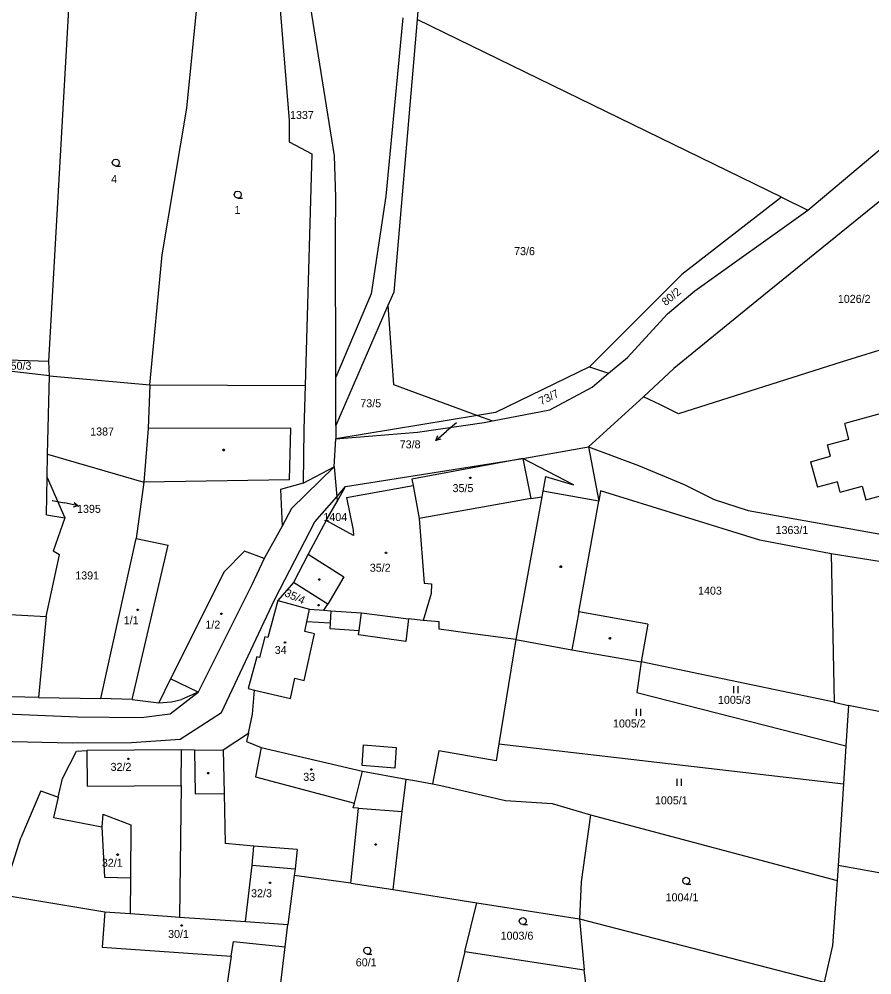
# Model space of a CAD drawing. Extents: x -852001 to -842497, y -1063614 to -1052182.
# Drawn here: x -844444 to -844262.9, y -1061526.1 to -1061323.1 of the extents above; entities that cross this region are included whole.
import ezdxf

# ---------------------------------------------------------------- set-up
doc = ezdxf.new("R2010")
doc.units = 0
for name, color, linetype in [('Default', 7, 'Continuous'), ('KN_HRANICE', 7, 'Continuous'), ('KN_KULTURY', 7, 'Continuous'), ('KN_PARCELY', 7, 'Continuous'), ('KN_SLUCKY', 7, 'Continuous')]:
    doc.layers.add(name, color=color, linetype=linetype)

# ---------------------------------------------------------------- blocks, each defined once
blk = doc.blocks.new('304')
at = {"layer": 'Default'}
blk.add_lwpolyline([(0, 0), (-0.38, 0.1), (-0.65, 0.37), (-0.75, 0.74), (-0.65, 1.11), (-0.38, 1.38), (-0.01, 1.48), (0.36, 1.38), (0.63, 1.11), (0.73, 0.73), (0.63, 0.35), (0.36, 0.08), (-0.02, -0.02), (0.98, -0.02)], dxfattribs=at)
blk = doc.blocks.new('306')
at = {"layer": 'Default'}
for p, q in [((-0.5, 1.5), (-0.5, 0)), ((0.5, 0), (0.5, 1.5))]:
    blk.add_line(p, q, dxfattribs=at)
blk = doc.blocks.new('NAHRADNI_SYMBOL')
at = {"layer": 'Default'}
blk.add_lwpolyline([(0.09, 0.15), (0.18, 0), (0.09, -0.15), (-0.09, -0.15), (-0.18, 0), (-0.09, 0.15), (0.09, 0.15)], dxfattribs=at)
blk = doc.blocks.new('10292')
at = {"layer": 'Default'}
blk.add_line((0, 3), (0, 0), dxfattribs=at)
blk.add_lwpolyline([(-0.5, 2), (0, 3), (0.5, 2)], dxfattribs=at)
blk = doc.blocks.new('402')
at = {"layer": 'Default'}
blk.add_lwpolyline([(0.09, 0.15), (0.18, 0), (0.09, -0.15), (-0.09, -0.15), (-0.18, 0), (-0.09, 0.15), (0.09, 0.15)], dxfattribs=at)

msp = doc.modelspace()

# ---------------------------------------------------------------- linework, layer by layer
at = {"layer": 'KN_HRANICE'}
for p, q in [((-844355.8, -1061278.6), (-844359.49, -1061323.11)), ((-844437.76, -1061395.7), (-844432.89, -1061310.51)), ((-844408.43, -1061341.94), (-844405.53, -1061312.84)), ((-844389.08, -1061315.26), (-844386.69, -1061344.57)), ((-844377.08, -1061352.12), (-844382.88, -1061315.51)), ((-844362.55, -1061322.76), (-844366.12, -1061360.65)), ((-844359.49, -1061323.11), (-844364.48, -1061381.09)), ((-844282.06, -1061360.88), (-844359.49, -1061323.11)), ((-844276.49, -1061363.63), (-844241.6, -1061334.29)), ((-844413.69, -1061373.1), (-844408.43, -1061341.94)), ((-844386.69, -1061344.57), (-844386.69, -1061349.14)), ((-844386.69, -1061349.14), (-844381.84, -1061351.65)), ((-844381.84, -1061351.65), (-844383.28, -1061400.88)), ((-844376.79, -1061360.87), (-844377.08, -1061352.12)), ((-844255.48, -1061357.05), (-844287.3, -1061382.9)), ((-844376.86, -1061369.32), (-844376.79, -1061360.87)), ((-844366.12, -1061360.65), (-844369.26, -1061381.41)), ((-844282.06, -1061360.88), (-844303.29, -1061377.34)), ((-844282.06, -1061360.88), (-844276.49, -1061363.63)), ((-844300.54, -1061380.81), (-844276.49, -1061363.63)), ((-844376.78, -1061399.14), (-844376.86, -1061369.32)), ((-844416.28, -1061400.77), (-844413.69, -1061373.1)), ((-844303.29, -1061377.34), (-844322.91, -1061396.91)), ((-844369.26, -1061381.41), (-844376.78, -1061399.14)), ((-844364.48, -1061381.09), (-844365.7, -1061383.91)), ((-844306.31, -1061385.64), (-844300.54, -1061380.81)), ((-844365.7, -1061383.91), (-844376.75, -1061409.41)), ((-844365.7, -1061383.91), (-844364.51, -1061400.66)), ((-844287.3, -1061382.9), (-844304.99, -1061397.3)), ((-844314.83, -1061394.93), (-844306.31, -1061385.64)), ((-844234.19, -1061384.88), (-844269.23, -1061395.89)), ((-844475.97, -1061394.54), (-844437.76, -1061395.7)), ((-844437.56, -1061398.83), (-844475.97, -1061394.54)), ((-844437.56, -1061398.83), (-844437.76, -1061395.7)), ((-844318.83, -1061398.3), (-844314.83, -1061394.93)), ((-844269.23, -1061395.89), (-844303.98, -1061406.9)), ((-844322.91, -1061396.91), (-844342.88, -1061406.62)), ((-844322.91, -1061396.91), (-844318.83, -1061398.3)), ((-844322.33, -1061401.24), (-844318.83, -1061398.3)), ((-844304.99, -1061397.3), (-844311.38, -1061403.28)), ((-844438.01, -1061415.47), (-844437.56, -1061398.83)), ((-844437.56, -1061398.83), (-844416.28, -1061400.77)), ((-844376.75, -1061409.41), (-844376.78, -1061399.14)), ((-844364.51, -1061400.66), (-844346.64, -1061407.24)), ((-844416.28, -1061400.77), (-844416.62, -1061410.01)), ((-844416.28, -1061400.77), (-844383.28, -1061400.88)), ((-844383.28, -1061400.88), (-844383.55, -1061410.22)), ((-844331.28, -1061406.1), (-844322.33, -1061401.24)), ((-844311.38, -1061403.28), (-844323.12, -1061413.92)), ((-844307.8, -1061405.03), (-844311.38, -1061403.28)), ((-844342.88, -1061406.62), (-844346.64, -1061407.24)), ((-844343.46, -1061408.4), (-844331.28, -1061406.1)), ((-844303.98, -1061406.9), (-844307.8, -1061405.03)), ((-844259.62, -1061406.48), (-844268.64, -1061408.96)), ((-844346.64, -1061407.24), (-844376.75, -1061412.24)), ((-844359.4, -1061410.79), (-844345.26, -1061408.74)), ((-844346.64, -1061407.24), (-844343.46, -1061408.4)), ((-844345.26, -1061408.74), (-844343.46, -1061408.4)), ((-844416.62, -1061410.01), (-844417.56, -1061421.43)), ((-844383.55, -1061410.22), (-844383.68, -1061421.62)), ((-844376.75, -1061409.41), (-844376.75, -1061412.24)), ((-844376.75, -1061412.24), (-844359.4, -1061410.79)), ((-844267.77, -1061412.3), (-844268.64, -1061408.96)), ((-844377.11, -1061418.19), (-844376.75, -1061412.24)), ((-844272.32, -1061413.52), (-844267.77, -1061412.3)), ((-844337.01, -1061416.42), (-844323.12, -1061413.92)), ((-844323.12, -1061413.92), (-844320.91, -1061425.5)), ((-844323.12, -1061413.92), (-844312.48, -1061417.88)), ((-844271.7, -1061415.94), (-844272.32, -1061413.52)), ((-844438.09, -1061420.42), (-844438.01, -1061415.47)), ((-844438.01, -1061415.47), (-844417.56, -1061421.43)), ((-844374.69, -1061422.36), (-844337.01, -1061416.42)), ((-844337.01, -1061416.42), (-844360.59, -1061420.77)), ((-844275.92, -1061417.08), (-844271.7, -1061415.94)), ((-844383.68, -1061421.62), (-844377.11, -1061418.19)), ((-844377.11, -1061418.19), (-844376.59, -1061424.54)), ((-844312.48, -1061417.88), (-844302.78, -1061421.94)), ((-844275.92, -1061417.08), (-844274.43, -1061422.48)), ((-844438.22, -1061428.35), (-844438.09, -1061420.42)), ((-844438.09, -1061420.42), (-844434.36, -1061428.99)), ((-844360.59, -1061420.77), (-844360.31, -1061422.11)), ((-844417.56, -1061421.43), (-844419.19, -1061433.37)), ((-844383.68, -1061421.62), (-844388.49, -1061423.02)), ((-844388.49, -1061423.02), (-844388.18, -1061430.75)), ((-844376.51, -1061425.55), (-844374.69, -1061422.36)), ((-844374.53, -1061424.7), (-844360.31, -1061422.11)), ((-844360.31, -1061422.11), (-844359.06, -1061429.16)), ((-844302.78, -1061421.94), (-844296.41, -1061425.13)), ((-844270.17, -1061421.34), (-844274.43, -1061422.48)), ((-844269.61, -1061423.58), (-844270.17, -1061421.34)), ((-844269.61, -1061423.58), (-844264.95, -1061422.29)), ((-844264.95, -1061422.29), (-844264.16, -1061425.17)), ((-844264.16, -1061425.17), (-844255.09, -1061422.7)), ((-844376.59, -1061424.54), (-844376.51, -1061425.55)), ((-844374.53, -1061424.7), (-844373.11, -1061431.65)), ((-844320.54, -1061423.3), (-844320.91, -1061425.5)), ((-844286.69, -1061433.79), (-844320.54, -1061423.3)), ((-844378.81, -1061429.57), (-844376.51, -1061425.55)), ((-844325.16, -1061448.99), (-844320.91, -1061425.5)), ((-844296.41, -1061425.13), (-844289.17, -1061427.44)), ((-844438.22, -1061428.35), (-844434.36, -1061428.99)), ((-844434.36, -1061428.99), (-844436.82, -1061436.08)), ((-844289.17, -1061427.44), (-844237.33, -1061436.72)), ((-844388.18, -1061430.75), (-844391.97, -1061437.66)), ((-844378.81, -1061429.57), (-844382.68, -1061436.7)), ((-844372.98, -1061432.73), (-844378.81, -1061429.57)), ((-844359.06, -1061429.16), (-844357.98, -1061442.87)), ((-844373.11, -1061431.65), (-844372.98, -1061432.73)), ((-844426.7, -1061467.38), (-844419.19, -1061433.37)), ((-844271.55, -1061436.64), (-844286.69, -1061433.79)), ((-844438.29, -1061449.97), (-844435.49, -1061436.86)), ((-844435.49, -1061436.86), (-844436.82, -1061436.08)), ((-844396.14, -1061436.12), (-844400.48, -1061440.48)), ((-844391.97, -1061437.66), (-844396.14, -1061436.12)), ((-844382.68, -1061436.7), (-844385.79, -1061442.75)), ((-844213.45, -1061446), (-844271.55, -1061436.64)), ((-844271.55, -1061436.64), (-844270.91, -1061468.18)), ((-844391.97, -1061437.66), (-844394.6, -1061443.25)), ((-844400.48, -1061440.48), (-844411.86, -1061463.19)), ((-844394.6, -1061443.25), (-844405.99, -1061466.08)), ((-844385.79, -1061442.75), (-844389.07, -1061446.6)), ((-844378.49, -1061447.34), (-844385.79, -1061442.75)), ((-844357.98, -1061442.87), (-844356.44, -1061443.03)), ((-844356.44, -1061443.03), (-844356.52, -1061445.06)), ((-844356.52, -1061445.06), (-844358.19, -1061450.8)), ((-844389.07, -1061446.6), (-844391.21, -1061454.46)), ((-844389.07, -1061446.6), (-844382.35, -1061448.45)), ((-844379.31, -1061448.65), (-844378.49, -1061447.34)), ((-844454.2, -1061449.07), (-844438.29, -1061449.97)), ((-844382.35, -1061448.45), (-844379.31, -1061448.65)), ((-844379.31, -1061448.65), (-844377.86, -1061448.74)), ((-844377.86, -1061448.74), (-844371.34, -1061449.16)), ((-844371.34, -1061449.16), (-844361.33, -1061450.48)), ((-844310.49, -1061451.61), (-844325.16, -1061448.99)), ((-844438.29, -1061449.97), (-844439.9, -1061467.16)), ((-844358.19, -1061450.8), (-844361.33, -1061450.48)), ((-844354.84, -1061451.14), (-844358.19, -1061450.8)), ((-844354.84, -1061452.65), (-844354.84, -1061451.14)), ((-844348.7, -1061453.49), (-844354.84, -1061452.65)), ((-844338.51, -1061454.86), (-844348.7, -1061453.49)), ((-844310.49, -1061451.61), (-844311.93, -1061459.63)), ((-844391.82, -1061454.3), (-844393.01, -1061458.7)), ((-844391.21, -1061454.46), (-844391.82, -1061454.3)), ((-844338.51, -1061454.86), (-844342.11, -1061477.05)), ((-844338.51, -1061454.86), (-844326.62, -1061457.05)), ((-844326.62, -1061457.05), (-844311.93, -1061459.63)), ((-844393.54, -1061458.56), (-844395.36, -1061465.26)), ((-844393.01, -1061458.7), (-844393.54, -1061458.56)), ((-844311.93, -1061459.63), (-844312.83, -1061466.13)), ((-844270.91, -1061468.18), (-844311.93, -1061459.63)), ((-844411.86, -1061463.19), (-844414.4, -1061468.34)), ((-844395.36, -1061465.26), (-844394.08, -1061465.63)), ((-844394.45, -1061470.71), (-844394.08, -1061465.63)), ((-844439.9, -1061467.16), (-844455.23, -1061466.77)), ((-844439.9, -1061467.16), (-844426.7, -1061467.38)), ((-844420.02, -1061467.61), (-844426.7, -1061467.38)), ((-844420.02, -1061467.61), (-844414.4, -1061468.34)), ((-844411.71, -1061468.09), (-844409.58, -1061467.62)), ((-844405.99, -1061466.08), (-844409.58, -1061467.62)), ((-844312.83, -1061466.13), (-844268.42, -1061477.46)), ((-844414.4, -1061468.34), (-844411.71, -1061468.09)), ((-844270.91, -1061468.18), (-844267.86, -1061468.88)), ((-844267.86, -1061468.88), (-844268.42, -1061477.46)), ((-844183.22, -1061486.06), (-844267.86, -1061468.88)), ((-844395.35, -1061474.75), (-844394.45, -1061470.71)), ((-844400.68, -1061478.33), (-844395.35, -1061474.75)), ((-844395.35, -1061474.75), (-844395.74, -1061476.53)), ((-844395.74, -1061476.53), (-844392.64, -1061477.84)), ((-844392.64, -1061477.84), (-844371.12, -1061482.83)), ((-844342.11, -1061477.05), (-844342.69, -1061480.64)), ((-844342.11, -1061477.05), (-844268.94, -1061485.5)), ((-844268.42, -1061477.46), (-844268.94, -1061485.5)), ((-844434.81, -1061484.41), (-844431.88, -1061478.59)), ((-844431.88, -1061478.59), (-844429.64, -1061478.44)), ((-844409.58, -1061478.29), (-844429.64, -1061478.44)), ((-844409.63, -1061485.89), (-844409.58, -1061478.29)), ((-844406.76, -1061478.35), (-844409.58, -1061478.29)), ((-844406.76, -1061478.35), (-844400.68, -1061478.33)), ((-844400.68, -1061478.33), (-844400.49, -1061487.61)), ((-844354.87, -1061478.49), (-844356.25, -1061485.54)), ((-844342.69, -1061480.64), (-844354.87, -1061478.49)), ((-844371.12, -1061482.83), (-844361.84, -1061484.51)), ((-844435.75, -1061488.39), (-844434.81, -1061484.41)), ((-844409.63, -1061485.89), (-844409.95, -1061513.82)), ((-844361.84, -1061484.51), (-844360.41, -1061484.77)), ((-844360.41, -1061484.77), (-844356.25, -1061485.54)), ((-844356.25, -1061485.54), (-844354.47, -1061485.87)), ((-844354.47, -1061485.87), (-844340.71, -1061489.06)), ((-844268.94, -1061485.5), (-844270.08, -1061502.89)), ((-844439.44, -1061487), (-844443.69, -1061496.99)), ((-844439.44, -1061487), (-844435.75, -1061488.39)), ((-844400.49, -1061487.61), (-844400.27, -1061498.23)), ((-844435.75, -1061488.39), (-844436.76, -1061492.67)), ((-844340.71, -1061489.06), (-844330.81, -1061489.72)), ((-844330.81, -1061489.72), (-844322.67, -1061492.14)), ((-844426.29, -1061491.95), (-844426.48, -1061494.63)), ((-844426.29, -1061491.95), (-844420.33, -1061494.26)), ((-844436.76, -1061492.67), (-844426.48, -1061494.63)), ((-844322.67, -1061492.14), (-844324.65, -1061506.34)), ((-844322.67, -1061492.14), (-844270.27, -1061506.03)), ((-844420.33, -1061494.26), (-844420.42, -1061505.52)), ((-844447.53, -1061509.13), (-844443.69, -1061496.99)), ((-844394.16, -1061498.74), (-844400.27, -1061498.23)), ((-844384.96, -1061499.51), (-844394.16, -1061498.74)), ((-844384.96, -1061499.51), (-844385.41, -1061503.58)), ((-844385.41, -1061503.58), (-844385.59, -1061504.98)), ((-844270.08, -1061502.89), (-844270.27, -1061506.03)), ((-844183.75, -1061518.46), (-844270.08, -1061502.89)), ((-844420.42, -1061505.52), (-844420.48, -1061513.08)), ((-844385.59, -1061504.98), (-844386.98, -1061515.43)), ((-844373.56, -1061506.62), (-844385.59, -1061504.98)), ((-844270.27, -1061506.03), (-844271.27, -1061519.86)), ((-844373.56, -1061506.62), (-844364.61, -1061507.99)), ((-844364.61, -1061507.99), (-844346.8, -1061510.8)), ((-844324.65, -1061506.34), (-844325.04, -1061514.23)), ((-844447.53, -1061509.13), (-844425.81, -1061512.7)), ((-844349.36, -1061521.16), (-844346.8, -1061510.8)), ((-844346.8, -1061510.8), (-844325.04, -1061514.23)), ((-844425.81, -1061512.7), (-844420.48, -1061513.08)), ((-844420.48, -1061513.08), (-844412.61, -1061513.63)), ((-844412.61, -1061513.63), (-844409.95, -1061513.82)), ((-844409.95, -1061513.82), (-844395.98, -1061514.79)), ((-844325.04, -1061514.23), (-844324.04, -1061525.01)), ((-844325.04, -1061514.23), (-844273.04, -1061527.65)), ((-844395.98, -1061514.79), (-844386.98, -1061515.43)), ((-844387.54, -1061520.17), (-844386.98, -1061515.43)), ((-844388.92, -1061531.86), (-844387.54, -1061520.17)), ((-844271.27, -1061519.86), (-844273.04, -1061527.65)), ((-844349.36, -1061521.16), (-844353.34, -1061537.33)), ((-844349.36, -1061521.16), (-844324.04, -1061525.01)), ((-844321.96, -1061541.94), (-844324.04, -1061525.01))]:
    msp.add_line(p, q, dxfattribs=at)
at = {"layer": 'KN_PARCELY'}
for p, q in [((-844351.14, -1061408.83), (-844353.26, -1061410.62)), ((-844437.02, -1061425.32), (-844434.44, -1061425.85))]:
    msp.add_line(p, q, dxfattribs=at)
at = {"layer": 'KN_SLUCKY'}
for p, q in [((-844386.31, -1061409.93), (-844416.62, -1061410.01)), ((-844386.59, -1061420.96), (-844386.31, -1061409.93)), ((-844326.27, -1061421.99), (-844337.01, -1061416.42)), ((-844337.01, -1061416.42), (-844335.33, -1061424.9)), ((-844377.11, -1061418.19), (-844386.16, -1061427.05)), ((-844386.59, -1061420.96), (-844417.56, -1061421.43)), ((-844332.2, -1061420.23), (-844332.77, -1061423.35)), ((-844332.2, -1061420.23), (-844326.27, -1061421.99)), ((-844376.59, -1061424.54), (-844374.69, -1061422.36)), ((-844381.24, -1061429.88), (-844376.59, -1061424.54)), ((-844335.33, -1061424.9), (-844344.39, -1061426.55)), ((-844333.04, -1061424.56), (-844338.51, -1061454.86)), ((-844335.33, -1061424.9), (-844333.04, -1061424.56)), ((-844332.77, -1061423.35), (-844333.04, -1061424.56)), ((-844320.91, -1061425.5), (-844332.77, -1061423.35)), ((-844386.16, -1061427.05), (-844388.18, -1061430.75)), ((-844344.39, -1061426.55), (-844359.06, -1061429.16)), ((-844389.74, -1061446.32), (-844381.24, -1061429.88)), ((-844420.02, -1061467.61), (-844412.4, -1061434.79)), ((-844419.19, -1061433.37), (-844412.4, -1061434.79)), ((-844382.68, -1061436.7), (-844375.1, -1061441.54)), ((-844375.1, -1061441.54), (-844378.49, -1061447.34)), ((-844401.05, -1061470.37), (-844389.74, -1061446.32)), ((-844382.92, -1061451.13), (-844382.35, -1061448.45)), ((-844377.86, -1061448.74), (-844377.98, -1061451.42)), ((-844371.8, -1061452.92), (-844371.34, -1061449.16)), ((-844325.16, -1061448.99), (-844326.62, -1061457.05)), ((-844383.36, -1061453.19), (-844382.92, -1061451.13)), ((-844377.98, -1061451.42), (-844382.92, -1061451.13)), ((-844377.98, -1061451.42), (-844378.02, -1061452.52)), ((-844361.33, -1061450.48), (-844361.9, -1061455.27)), ((-844381.3, -1061453.64), (-844383.36, -1061453.19)), ((-844378.02, -1061452.52), (-844371.8, -1061452.92)), ((-844371.92, -1061453.88), (-844371.8, -1061452.92)), ((-844383.47, -1061463.57), (-844381.3, -1061453.64)), ((-844361.9, -1061455.27), (-844371.92, -1061453.88)), ((-844405.99, -1061466.08), (-844411.86, -1061463.19)), ((-844386.39, -1061467.4), (-844385.48, -1061463.11)), ((-844385.48, -1061463.11), (-844383.47, -1061463.57)), ((-844394.08, -1061465.63), (-844386.39, -1061467.4)), ((-844411.98, -1061470.66), (-844405.99, -1061466.08)), ((-844469.55, -1061469.78), (-844431.61, -1061471.3)), ((-844431.61, -1061471.3), (-844418.1, -1061471.4)), ((-844418.1, -1061471.4), (-844411.98, -1061470.66)), ((-844409.83, -1061476.01), (-844401.05, -1061470.37)), ((-844468.98, -1061476.02), (-844432.78, -1061476.81)), ((-844432.78, -1061476.81), (-844420.2, -1061476.77)), ((-844420.2, -1061476.77), (-844409.83, -1061476.01)), ((-844392.64, -1061477.84), (-844393.8, -1061484.06)), ((-844371.15, -1061481.62), (-844370.87, -1061477.27)), ((-844370.87, -1061477.27), (-844363.93, -1061477.78)), ((-844363.93, -1061477.78), (-844364.22, -1061482.18)), ((-844429.64, -1061478.44), (-844429.6, -1061486.01)), ((-844406.76, -1061478.35), (-844406.66, -1061487.65)), ((-844364.22, -1061482.18), (-844371.15, -1061481.62)), ((-844372.78, -1061489.61), (-844371.12, -1061482.83)), ((-844429.6, -1061486.01), (-844409.63, -1061485.89)), ((-844393.8, -1061484.06), (-844372.78, -1061489.61)), ((-844362.65, -1061491.38), (-844361.84, -1061484.51)), ((-844406.66, -1061487.65), (-844400.49, -1061487.61)), ((-844373.06, -1061490.65), (-844372.78, -1061489.61)), ((-844373.56, -1061506.62), (-844371.98, -1061490.72)), ((-844371.98, -1061490.72), (-844373.06, -1061490.65)), ((-844371.98, -1061490.72), (-844362.65, -1061491.38)), ((-844364.61, -1061507.99), (-844362.65, -1061491.38)), ((-844426.48, -1061494.63), (-844425.9, -1061505.34)), ((-844394.54, -1061502.78), (-844394.16, -1061498.74)), ((-844395.98, -1061514.79), (-844394.54, -1061502.78)), ((-844394.54, -1061502.78), (-844385.41, -1061503.58)), ((-844425.9, -1061505.34), (-844420.42, -1061505.52)), ((-844425.81, -1061512.7), (-844426.4, -1061520.2)), ((-844426.4, -1061520.2), (-844399.03, -1061522.17)), ((-844399.03, -1061522.17), (-844398.54, -1061519)), ((-844398.54, -1061519), (-844387.54, -1061520.17)), ((-844399.03, -1061522.17), (-844401.68, -1061540.59))]:
    msp.add_line(p, q, dxfattribs=at)

# ---------------------------------------------------------------- block references
at = {"layer": 'KN_KULTURY'}
for name, p in [('304', (-844423.51, -1061354.28)), ('304', (-844397.6, -1061361.08)), ('402', (-844400.59, -1061414.6)), ('402', (-844348.18, -1061420.51)), ('402', (-844366.11, -1061436.46)), ('402', (-844328.97, -1061439.38)), ('402', (-844380.3, -1061442.09)), ('402', (-844418.87, -1061448.58)), ('402', (-844401.09, -1061449.43)), ('NAHRADNI_SYMBOL', (-844380.44, -1061447.58)), ('402', (-844387.55, -1061455.48)), ('402', (-844318.55, -1061454.62)), ('306', (-844291.78, -1061466.24)), ('306', (-844312.5, -1061471.07)), ('402', (-844420.82, -1061480.21)), ('402', (-844403.89, -1061483.28)), ('402', (-844381.96, -1061482.48)), ('306', (-844303.86, -1061485.94)), ('402', (-844368.29, -1061498.43)), ('402', (-844423.12, -1061500.58)), ('304', (-844302.34, -1061506.85)), ('402', (-844390.76, -1061506.58)), ('304', (-844337.04, -1061515.42)), ('402', (-844409.5, -1061515.64)), ('304', (-844370.08, -1061521.69))]:
    msp.add_blockref(name, p, dxfattribs=at)
at = {"layer": 'KN_PARCELY'}
for p, rotation in [((-844353.26, -1061410.62), 130.061419), ((-844434.44, -1061425.85), -101.65332999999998)]:
    msp.add_blockref('10292', p, dxfattribs=dict(at, rotation=rotation))

# ---------------------------------------------------------------- texts
for s, height, p in [('1337', 1.7, (-844386.5, -1061344.27)), ('4', 1.7, (-844424.5, -1061357.89)), ('1', 1.7, (-844398.29, -1061364.45)), ('73/6', 1.7, (-844338.9, -1061373.2)), ('1026/2', 1.7, (-844270.13, -1061383.34)), ('250/3', 1.7, (-844447.13, -1061397.55)), ('73/5', 1.7, (-844371.57, -1061405.52)), ('73/8', 0.1, (-844351.34, -1061408.83)), ('1387', 1.7, (-844428.95, -1061411.52)), ('73/8', 1.7, (-844363.2, -1061414.25)), ('35/5', 1.7, (-844351.97, -1061423.55)), ('1395', 0.1, (-844437.22, -1061425.32)), ('1395', 1.7, (-844431.74, -1061427.95)), ('1404', 1.7, (-844379.41, -1061429.68)), ('1363/1', 1.7, (-844283.35, -1061432.45)), ('35/2', 1.7, (-844369.55, -1061440.46)), ('1391', 1.7, (-844432.12, -1061442.1)), ('1403', 1.7, (-844299.82, -1061445.33)), ('1/1', 1.7, (-844421.83, -1061451.61)), ('1/2', 1.7, (-844404.48, -1061452.55)), ('34', 1.7, (-844389.75, -1061457.93)), ('1005/3', 1.7, (-844295.59, -1061468.53)), ('1005/2', 1.7, (-844317.89, -1061473.55)), ('32/2', 1.7, (-844424.62, -1061482.77)), ('33', 1.7, (-844383.69, -1061484.9)), ('1005/1', 1.7, (-844308.98, -1061489.88)), ('32/1', 1.7, (-844426.47, -1061503.15)), ('32/3', 1.7, (-844394.77, -1061509.62)), ('1004/1', 1.7, (-844306.71, -1061510.49)), ('30/1', 1.7, (-844412.4, -1061518.27)), ('1003/6', 1.7, (-844341.76, -1061518.64)), ('60/1', 1.7, (-844372.53, -1061524.3))]:
    msp.add_text(s, height=height, dxfattribs=at).set_placement(p)
for s, rotation, p in [('80/2', 39.591, (-844306.69, -1061384.07)), ('73/7', 26.299, (-844333.15, -1061405.12)), ('35/4', 335.409, (-844387.81, -1061445.58))]:
    msp.add_text(s, height=1.7, rotation=rotation, dxfattribs=at).set_placement(p)

doc.saveas('drawing.dxf')
